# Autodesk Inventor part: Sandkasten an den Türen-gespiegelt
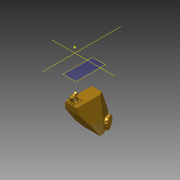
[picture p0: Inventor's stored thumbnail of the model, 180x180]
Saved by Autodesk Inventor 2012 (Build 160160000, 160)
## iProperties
Created: 2011-11
Part Number: Sandkasten an den Türen-gespiegelt
Material: Default
Document SubType Name: Modeling
Designer: Hans-Jürgen
Density: 1 g/cm^3
Author: Hans-Jürgen
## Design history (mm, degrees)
sketch "Skizze1"
  geometry: L1 (0, 7)-(0, 23); L2 (0, 23)-(10, 23); L3 (12.88, 7)-(12.88, 17); L4 (12.88, 17)-(10, 23); L5 (12.88, 7)-(0, 7); 1 further point
  constraints: 10 end point, 1 parallel, 1 perpendicular, 1 vertical
  dimensions: "d0" = 10 distance from line of L2.end L1; "d14" = 154.359 deg angle of L4 L3; "d16" = 12.88 distance between parallel lines of L1 L3; "d31" = 16 distance of L1.start L1.end; "d38" = 6.6554 distance of L3.end L2.end (derived)
extrude "Extrusion1" new body sketch "Skizze1" distance "d17" = 15.5; taper "d18" = 0 deg
workplane "Arbeitsebene1"
sketch "Skizze8"
  geometry: L1 (0, 23)-(10, 23) reference; L2 (0, 7)-(0, 23) reference; L3 (12.88, 7)-(0, 7) reference; L4 (12.88, 17)-(12.88, 7) reference; L5 (10, 23)-(12.88, 17) reference; L6 (12.88, 15)-(0, 15); 1 further point
  constraints: 2 end point, 1 midpoint, 1 perpendicular, 1 point on line
  dimensions: "d39" = 8 distance between parallel lines of L3 L6
sketch "Skizze9"
  geometry: L1 (12.88, 15.5)-(0, 15.5) reference; L2 (0, 0)-(0, 15.5) reference; L3 (0, 0)-(12.88, 0) reference; L4 (12.88, 0)-(12.88, 15.5) reference; L5 (0, 3.5)-(12.88, 3.5)
  constraints: 2 end point, 2 point on line, 1 perpendicular
  dimensions: "d40" = 12 distance between parallel lines of L1 L5
workplane "Arbeitsebene2"
  workaxis "Arbeitsachse1"
  workaxis "Arbeitsachse2"
feature "Trennen1"
sketch "Skizze10"
  geometry: L1 (15.5, 0)-(15.5, 6.655) reference; L2 (15.5, 6.655)-(0, 6.655) reference; L3 (15.5, 0)-(0, 0) reference; L4 (0, 6.655)-(7.5, 6.655); L5 (7.5, 6.655)-(7.5, 0); L6 (7.5, 0)-(0, 0); C1 r 2.75 at (4, 3.655); 1 further point
  constraints: 6 end point, 2 point on line, 1 centre point, 1 collinear, 1 perpendicular
  dimensions: "d42" = 7.5 distance of L2.end L4.end; "d43" = 5.5 diameter of C1; "d45" = 3 distance from line of C1.centre L2; "d46" = 11.5 distance from line of C1.centre L1
sketch "Skizze11"
  geometry: L1 (0, -15.5)-(10, -15.5) reference; L2 (10, 0)-(10, -15.5) reference; L3 (10, 0)-(0, 0) reference; L4 (0, 0)-(0, -15.5) reference; L5 (10, -8)-(12.88, -8) reference; L6 (10, -8)-(6, 0)
  constraints: 2 end point, 1 point on line
  dimensions: "d47" = 4 distance of L6.end L2.start
workplane "Arbeitsebene3"
feature "Trennen2"
sketch "Skizze12"
  geometry: L1 (-12.88, 7)-(-12.88, 8.667) reference; L2 (0, 7)-(-12.88, 7) reference; L3 (0, 23)-(0, 7) reference; L4 (-6, 23)-(0, 23) reference; L5 (-6.96, 21)-(0, 21); L6 (-6.96, 21)-(-6.96, 7); 2 further points; 1 other entity
  constraints: 4 end point, 2 perpendicular, 2 point on line, 2 other
  dimensions: "d48" = 2 distance between parallel lines of L4 L5
sketch "Skizze13"
  geometry: L1 (-8.775, 14.168)-(0, 15.899) reference; L2 (-8.775, 7.513)-(-8.775, 14.168) reference; L3 (0, 13.681)-(2.578, 16.692) reference; L4 (0, 13.681)-(0, 15.899); L5 (-8.775, 7.513)-(-15.613, 7.513) reference; L6 (0, 13.681)-(-8.775, 7.513); L7 (-8.775, 7.513)-(-13.117, 4.461); L8 (0, 0.462)-(-0.367, 0.376) reference; L9 (0, 15.899)-(0, 0) reference; 4 further points; 2 other entities
  constraints: 6 end point, 1 collinear, 1 parallel, 3 other
workplane "Arbeitsebene5"
  workaxis "Arbeitsachse3"
feature "Trennen4"
extrude "Extrusion6" join sketch "Skizze10" distance "d55" = 0.8; taper "d56" = 0 deg
workplane "Arbeitsebene7"
sketch "Skizze16"
  geometry: L1 (8, 0)-(16, 0) reference; L2 (0, -10.392)-(8, 0) reference; L3 (9.133, 0)-(8.224, -1.983); L4 (8, 0)-(11.786, 0); L5 (8, 0)-(6.17, -2.377); L6 (6.17, -2.377)-(11.786, 0); 1 further point
  constraints: 8 end point, 3 point on line
  dimensions: "d62" = 3 distance from line of L2 L4.end; "d63" = 3 distance of L1.start L5.end
extrude "Extrusion7" cut sketch "Skizze16" stored distance "d59" = 10; taper "d60" = 0 deg
sketch "Skizze17"
  geometry: L1 (0, 16)-(15.5, 16) reference; L2 (0, 16)-(0, 0) reference; C1 r 1.427 at (8, 12); 1 further point
  constraints: 1 centre point
  dimensions: "d64" = 4 distance from line of L1 C1.centre; "d65" = 8 distance from line of L2 C1.centre
extrude "Extrusion8" join sketch "Skizze17" distance "d66" = 8; taper "d67" = 0 deg
sketch "Skizze18"
  geometry: L1 (3.5, 3)-(-4, 3) reference; L2 (3.5, -3.655)-(-4, -3.655) reference; C1 r 2.75 at (0, 0) reference; C2 r 3.5 at (0, 0); 1 further point
  constraints: 1 centre point, 1 coincident
  dimensions: "d68" = 7 diameter of C2
extrude "Extrusion9" join sketch "Skizze18" distance "d69" = 0.8; taper "d70" = 0 deg
sketch "Skizze19"
  geometry: A1 r 3.5 centre (0, 0) between (0, 3.5) and (-1.294, 3.252); A2 r 1.736 centre (-0.95, 4.954) between (-1.294, 3.252) and (0, 3.5); 1 further point
  constraints: 4 point on circle, 2 centre point
extrude "Extrusion10" cut sketch "Skizze19" distance "d71" = 0.8; taper "d72" = 0 deg
pattern_circular "Runde Anordnung1" dims angle "d74" = 360 deg
sketch "Skizze20"
  geometry: L1 (-6.96, 21)-(-6.96, 7) reference; L2 (-4.96, 12.452)-(-0.96, 12.452); L3 (-0.96, 12.452)-(-0.96, 7.452); L4 (-0.96, 7.452)-(-4.96, 7.452); L5 (-4.96, 7.452)-(-4.96, 12.452); L6 (-4.645, 11.488)-(-4.817, 11.917); L7 (-4.817, 11.917)-(-4.532, 12.28); L8 (-4.532, 12.28)-(-4.075, 12.215); L9 (-4.075, 12.215)-(-3.903, 11.786); L10 (-3.903, 11.786)-(-4.188, 11.423); L11 (-4.188, 11.423)-(-4.645, 11.488); L12 (-2, 11.712)-(-1.901, 12.163); L13 (-1.901, 12.163)-(-1.46, 12.303); L14 (-1.46, 12.303)-(-1.12, 11.991); L15 (-1.12, 11.991)-(-1.219, 11.54); L16 (-1.219, 11.54)-(-1.66, 11.401); L17 (-1.66, 11.401)-(-2, 11.712); L18 (-1.196, 7.767)-(-1.625, 7.594); L19 (-1.625, 7.594)-(-1.988, 7.879); L20 (-1.988, 7.879)-(-1.924, 8.336); L21 (-1.924, 8.336)-(-1.495, 8.509); L22 (-1.495, 8.509)-(-1.132, 8.224); L23 (-1.132, 8.224)-(-1.196, 7.767); L24 (-4.818, 7.995)-(-4.638, 8.421); L25 (-4.638, 8.421)-(-4.18, 8.477); L26 (-4.18, 8.477)-(-3.902, 8.108); L27 (-3.902, 8.108)-(-4.082, 7.683); L28 (-4.082, 7.683)-(-4.54, 7.627); L29 (-4.54, 7.627)-(-4.818, 7.995); C1 r 0.3 at (-4.36, 11.852); C2 r 0.3 at (-1.56, 11.852); C3 r 0.3 at (-4.36, 8.052); C4 r 0.3 at (-1.56, 8.052); 5 further points
  constraints: 56 end point, 4 centre point, 4 coincident, 2 parallel, 1 horizontal, 1 perpendicular, 52 other
  dimensions: "d76" = 5 distance of L2.end L3.end; "d77" = 4 distance of L3.end L4.end; "d78" = 2 distance between parallel lines of L5 L1; "d79" = 0.6 distance from line of L5 C1.centre; "d80" = 0.6 distance from line of L2 C1.centre; "d81" = 0.6 distance from line of L2 C2.centre; "d82" = 0.6 distance from line of L3 C2.centre; "d83" = 0.6 diameter of C2; "d84" = 0.6 diameter of C1; "d85" = 0.6 diameter of C3; "d86" = 0.6 diameter of C4; "d87" = 0.6 distance from line of L4 C3.centre; "d88" = 0.6 distance from line of L5 C3.centre; "d89" = 0.6 distance from line of L3 C4.centre; "d90" = 0.6 distance from line of C4.centre L4; "d91" = 0.8 distance between parallel lines of L9 L6; "d92" = 0.8 distance between parallel lines of L14 L17; "d93" = 0.8 distance between parallel lines of L26 L29; "d94" = 0.8 distance from line of L22.end L19
extrude "Extrusion11" join sketch "Skizze20" distance "d95" = 0.5; taper "d96" = 0 deg
extrude "Extrusion12" join sketch "Skizze20" distance "d97" = 0.8; taper "d98" = 0 deg
extrude "Extrusion13" join sketch "Skizze20" distance "d99" = 1; taper "d100" = 0 deg
sketch "Skizze21" dims "d101" = 1.35122, "d102" = 2.09243
  geometry: L1 (-0.96, 12.452)-(-0.96, 7.452) reference; L2 (-0.96, 7.452)-(-4.96, 7.452) reference; 2 further points; 1 other entity
  constraints: 1 horizontal, 2 other
  dimensions: "d103" = 2 distance from line of point (-2.96, 9.952) L1; "d104" = 2.5 distance from line of point (-2.96, 9.952) L2
workplane "Arbeitsebene8"
sketch "Skizze22"
  geometry: L1 (-2.96, 9.952)-(-2.96, 8.452); C1 r 1.5 at (-2.96, 8.452); 1 further point
  constraints: 2 end point, 1 centre point, 1 coincident, 1 vertical
  dimensions: "d106" = 1.5 distance of L1.start L1.end; "d107" = 3 diameter of C1
feature "Erhebung2" sketch "Skizze22" dims "d108" = 0, "d109" = 90 deg, "d110" = 0, "d111" = 90 deg
workaxis "Arbeitsachse4"
fillet "Rundung1" dims "d113" = 0.75
workpoint "Arbeitspunkt1"
workplane "Arbeitsebene9"
  workaxis "Arbeitsachse5"
sketch "Skizze23"
  geometry: L1 (2, -3.464)-(2, -4.041) reference; L2 (2, -4.041)-(4, -4.041) reference; L3 (4, -4.041)-(9.92, -13.279) reference; L4 (-2.96, -4.041)-(-2, -4.041) reference; L5 (-2, -4.041)-(-2, -3.464) reference; L6 (-2, -3.464)-(-1.773, -3.464) reference; L7 (0.758, -3.464)-(-0.758, -3.464) reference; L8 (-1.351, -2.598)-(-1.461, -0.128) reference; L9 (8.038, -21.939)-(-2.96, -21.939) reference; L10 (-2.96, -21.939)-(-2.96, -4.041) reference; L11 (-1.773, -3.464)-(-1.741, -3.177) reference; L12 (-1.741, -3.177)-(-1.648, -3.118) reference; L13 (-1.648, -3.118)-(-1.18, -3.118) reference; L14 (-1.18, -3.118)-(-0.991, -3.464) reference; L15 (-0.991, -3.464)-(1.023, -3.464) reference; L16 (1.023, -3.464)-(1.159, -3.118) reference; L17 (1.159, -3.118)-(1.694, -3.118) reference; L18 (1.694, -3.118)-(1.764, -3.464) reference; L19 (1.764, -3.464)-(2, -3.464) reference; L20 (9.92, -13.279)-(9.92, -14.097) reference; L21 (9.92, -14.097)-(9.438, -16.106) reference; L22 (10.215, -16.564)-(10.422, -15.702) reference; L23 (11.173, -16.27)-(10.016, -21.091) reference; L24 (9.067, -21.349)-(9.285, -20.438) reference; L25 (8.385, -20.494)-(8.038, -21.939) reference; L26 (2, -3.848)-(-2, -3.848) reference; C1 r 0.75 at (0, 0); 12 further points; 7 other entities
  constraints: 1 centre point, 1 horizontal alignment, 12 other
  dimensions: "d120" = 1.5 diameter of C1
extrude "Extrusion16" join sketch "Skizze23" stored distance "d123" = 2; taper "d124" = 0 deg
sketch "Skizze24"
  geometry: L1 (0.228, -1.014)-(-0.764, -0.705); L2 (-0.764, -0.705)-(-0.992, 0.309); L3 (-0.992, 0.309)-(-0.228, 1.014); L4 (-0.228, 1.014)-(0.764, 0.705); L5 (0.764, 0.705)-(0.992, -0.309); L6 (0.992, -0.309)-(0.228, -1.014); C1 r 0.75 at (0, 0) reference; 2 further points
  constraints: 12 end point, 1 coincident, 13 other
  dimensions: "d125" = 1.8 distance between parallel lines of L6 L3
extrude "Extrusion17" join sketch "Skizze24" distance "d126" = 0.8; taper "d127" = 0 deg
sketch "Skizze25"
  geometry: C1 r 0.75 at (0, 0) reference; C2 r 0.5 at (0, 0); 1 further point
  constraints: 1 centre point, 1 coincident
  dimensions: "d128" = 1 diameter of C2
extrude "Extrusion18" cut sketch "Skizze25" distance "d129" = 0.5; taper "d130" = 0 deg
workplane "Arbeitsebene10"
mirror "Spiegeln2"
mirror "Spiegeln3"
node "Volumenkörper1"
node "Volumenkörper2"
node "Projizierte Kontur2"
node "Schnittkanten projizieren1"
other parameters: "d19" = 9, "d61" = 60 deg, "d114" = 3, "d119" = 60 deg, "d131" = 14.25
